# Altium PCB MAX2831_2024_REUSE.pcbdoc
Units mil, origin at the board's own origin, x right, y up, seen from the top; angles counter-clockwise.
Board outline 3396.87 x 1187.57 mil, 6 copper layers (Top Layer, Inner1, Inner2, Inner3, Inner4, Bottom Layer); 31 components, 42 nets, 128 pads, 28 vias.
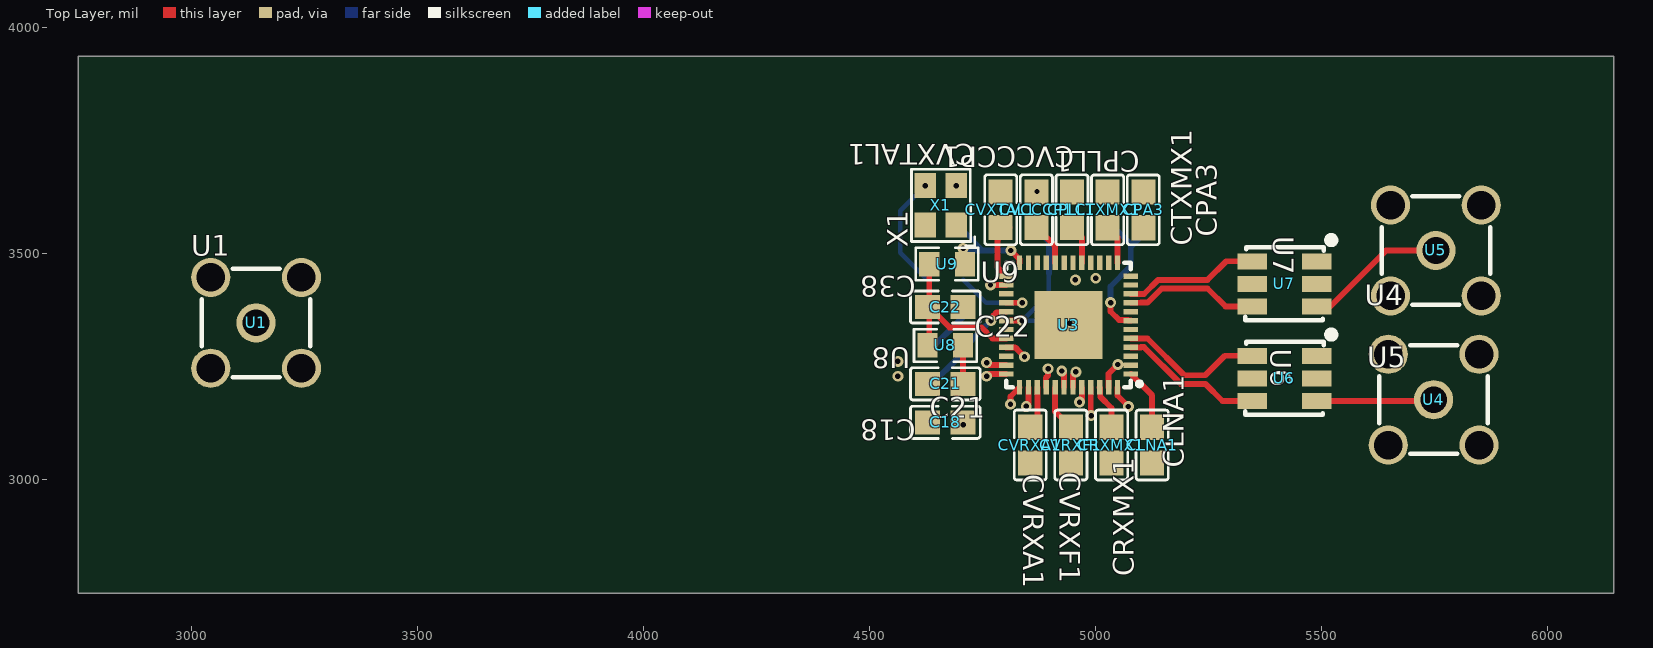
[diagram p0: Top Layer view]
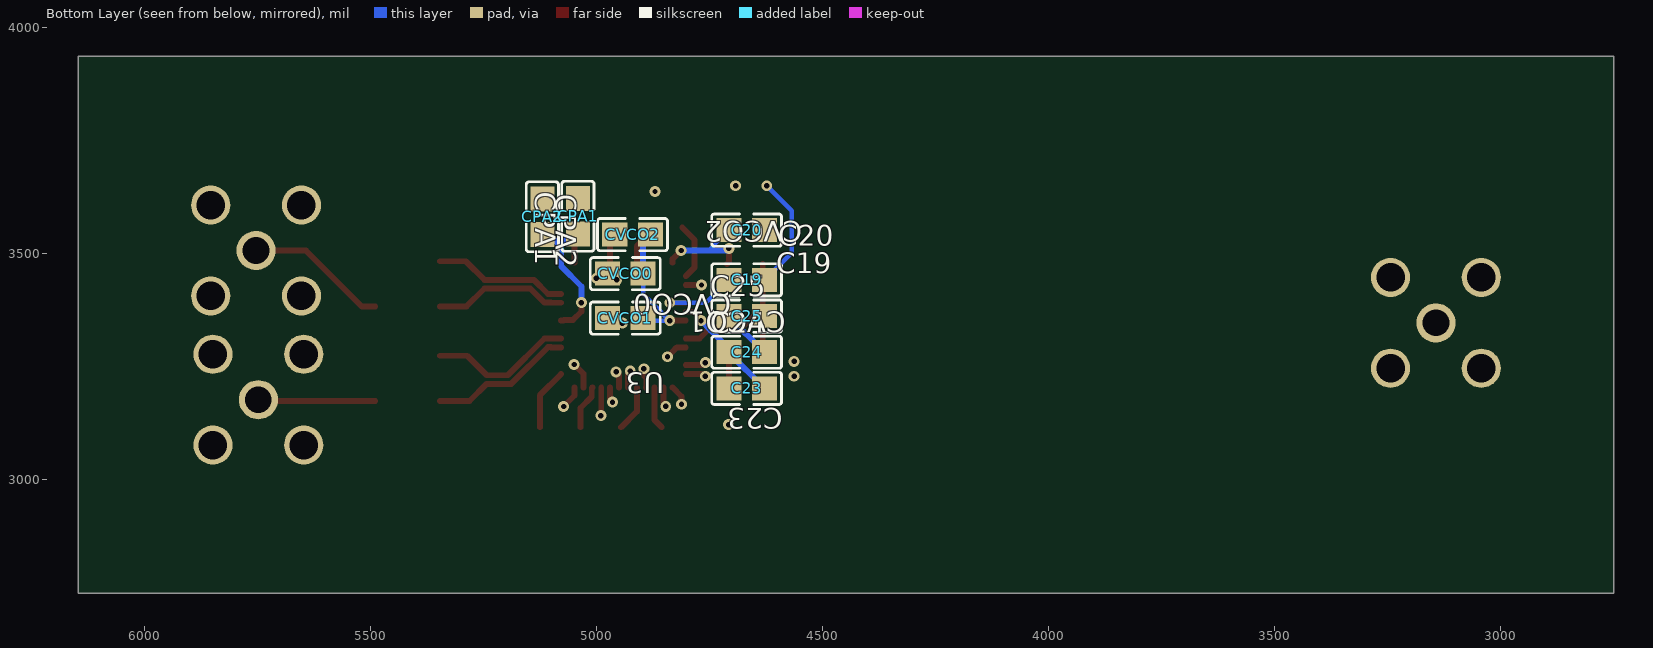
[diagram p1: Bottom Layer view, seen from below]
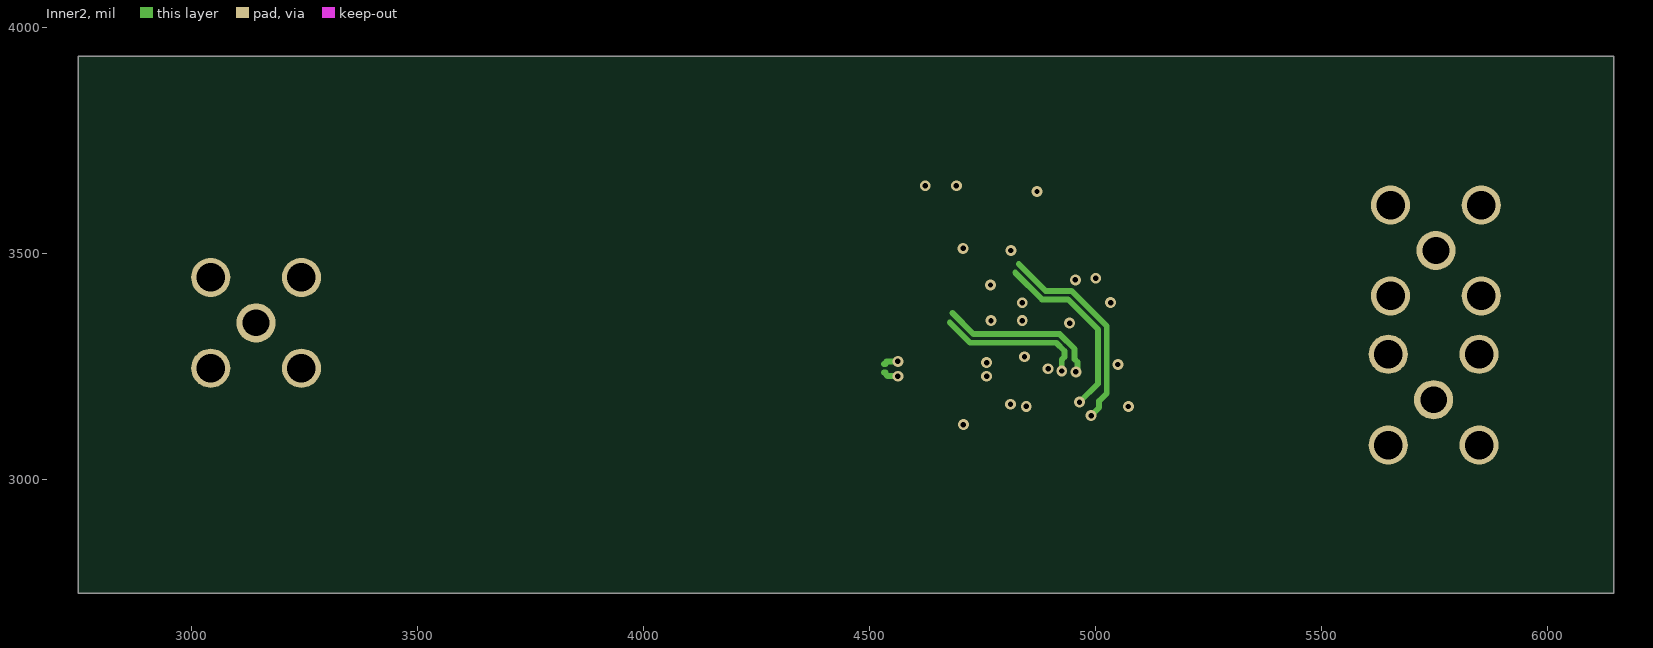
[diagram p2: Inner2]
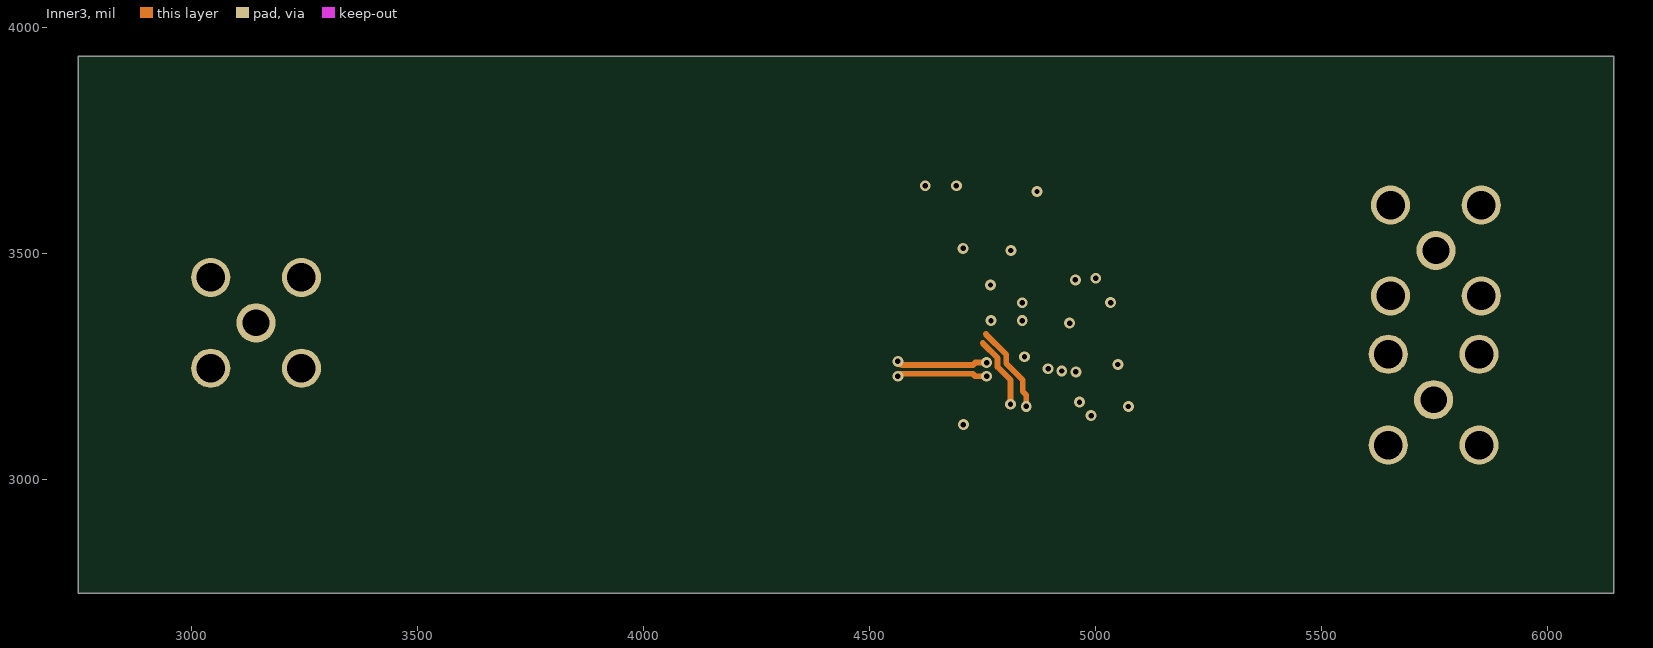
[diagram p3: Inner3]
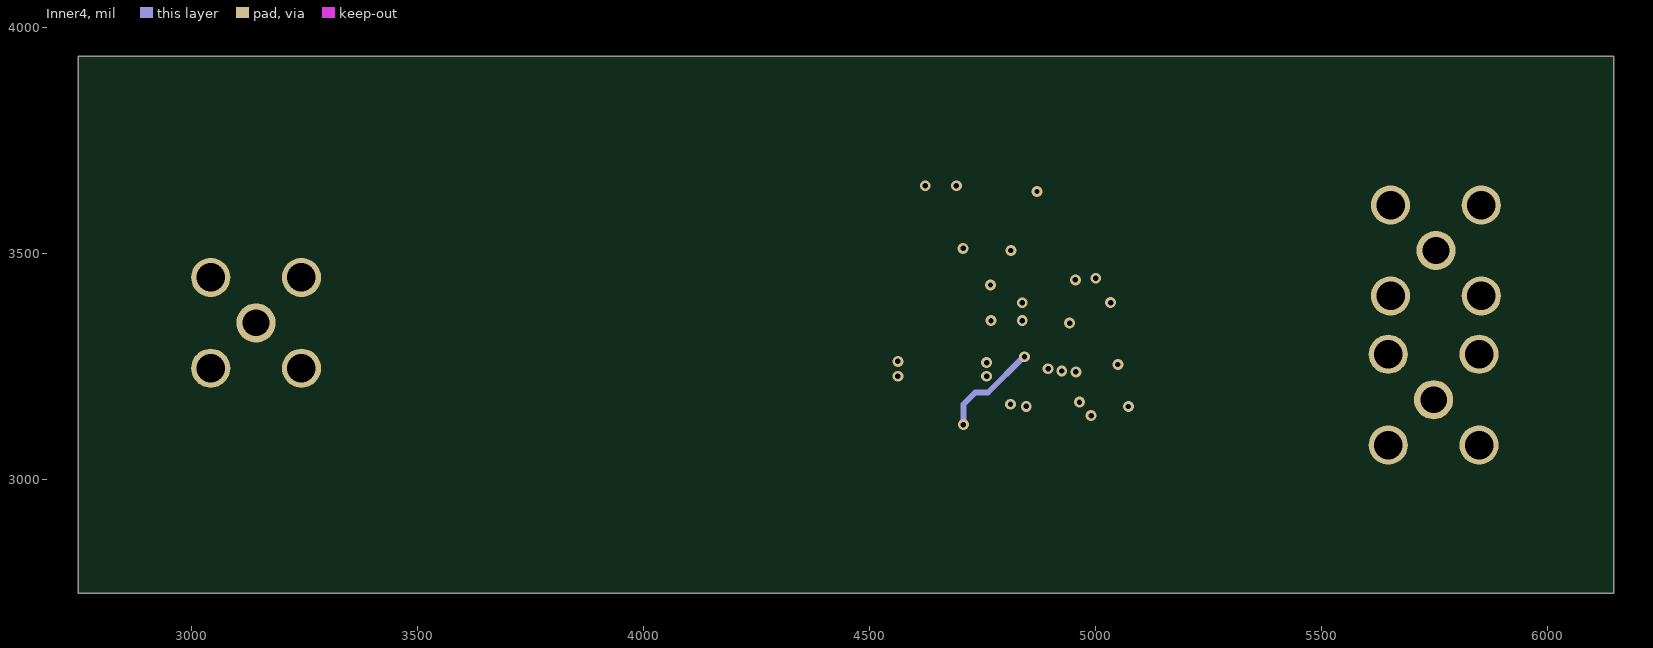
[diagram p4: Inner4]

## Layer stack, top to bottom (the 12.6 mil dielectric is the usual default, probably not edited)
Top Layer: signal copper (thickness not stored)
Dielectric: dielectric 12.6, FR-4, Dk 4.8
Inner1: signal copper (thickness not stored)
Dielectric: dielectric 12.6, FR-4, Dk 4.8
Inner2: signal copper (thickness not stored)
Dielectric: dielectric 12.6, FR-4, Dk 4.8
Inner3: signal copper (thickness not stored)
Dielectric: dielectric 12.6, FR-4, Dk 4.8
Inner4: signal copper (thickness not stored)
Dielectric: dielectric 12.6, FR-4, Dk 4.8
Bottom Layer: signal copper (thickness not stored)

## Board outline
6146.87,2750 2750,2750 2750,3937.57 6146.87,3937.57

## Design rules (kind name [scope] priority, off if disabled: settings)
BoardOutlineClearance copperThickness1oz [All] p0: genericclearance=10 ignorepadtopadclearanceinfootprint=FALSE except(0: Arc-SplitContinuation Track-SplitContinuation SMDPad-SplitContinuation THPad-SplitContinuation Via-SplitContinuation Fill-SplitContinuation Poly-SplitContinuation Region-SplitContinuation Text-SplitContinuation; 6: Track-CutoutEdge SMDPad-CutoutEdge THPad-CutoutEdge Via-CutoutEdge Region-CutoutEdge; 11.8: Track-OutlineEdge SMDPad-OutlineEdge THPad-OutlineEdge Via-OutlineEdge Fill-OutlineEdge Region-OutlineEdge Poly-OutlineEdge Text-OutlineEdge Fill-CutoutEdge)
BoardOutlineClearance copperThickness2oz [All] p0: genericclearance=10 ignorepadtopadclearanceinfootprint=FALSE except(0: Arc-SplitContinuation Track-SplitContinuation SMDPad-SplitContinuation THPad-SplitContinuation Via-SplitContinuation Fill-SplitContinuation Poly-SplitContinuation Region-SplitContinuation Text-SplitContinuation; 6: Track-CutoutEdge SMDPad-CutoutEdge THPad-CutoutEdge Via-CutoutEdge Region-CutoutEdge; 11.8: Track-OutlineEdge SMDPad-OutlineEdge THPad-OutlineEdge Via-OutlineEdge Fill-OutlineEdge Region-OutlineEdge Poly-OutlineEdge Text-OutlineEdge Fill-CutoutEdge)
Clearance copperThickness1oz [(InNet('3.3') OR InNet('GND') OR InNet('RXQN') OR InNet('RXQP') OR InNet('RXIN') OR InNet('RXIP') OR InNet('TXQN') OR InNet('TXQP') OR InNet('TXIN') OR InNet('TXIP') OR InNet('$1I297\$1N2490') OR InNet('$1I297\$1N2254') OR InNet('$1I297\XTAL') OR InNet('$1I297\CPOUT') OR InNet('$1I297\RXN') OR InNet('$1I297\TXN') OR InNet('$1I297\RXP') OR InNet('$1I297\TXP') OR InNet('$1I297\$1N1514') OR InNet('$1I297\$1N1513') OR InNet('$1I297\BYPASS') OR InNet('$1I297\RXTX_MODE') OR InNet('$1I297\RXHP') OR InNet('$1I297\TUNE') OR InNet('$1I297\$1N1515') OR InNet('REF') OR InNet('$1I297\SHDN#') OR InNet('+5V') OR InNet('$1I297\D6') OR InNet('$1I297\D7') OR InNet('$1I297\D3') OR InNet('$1I297\D2') OR InNet('$1I297\D4') OR InNet('$1I297\D5') OR InNet('$1I297\CS#') OR InNet('$1I297\RSSI') OR InNet('$1I297\SCLK') OR InNet('$1I297\DIN') OR InNet('$1I297\CLKBUF') OR InNet('$1I297\PLL_LOCK') OR InNet('$1I297\D1') OR InNet('$1I297\$1N3884'))] p1: gap=7 ignorepadtopadclearanceinfootprint=FALSE except(4: Track-Track; 6: Track-SMDPad SMDPad-SMDPad Track-THPad SMDPad-THPad THPad-THPad Track-Via SMDPad-Via THPad-Via Via-Via SMDPad-Fill THPad-Fill Via-Fill Fill-Fill Track-Region SMDPad-Region THPad-Region Via-Region Region-Region Track-Poly SMDPad-Poly THPad-Poly Via-Poly Fill-Poly Region-Poly Poly-Poly Track-Text SMDPad-Text THPad-Text Via-Text Fill-Text Region-Text Poly-Text Text-Text; 6.9: Track-Hole SMDPad-Hole THPad-Hole Via-Hole Fill-Hole Region-Hole Poly-Hole Text-Hole Sheet-Hole; 11.8: Track-Fill Fill-Region Track-Sheet SMDPad-Sheet THPad-Sheet Via-Sheet Fill-Sheet Region-Sheet Poly-Sheet Text-Sheet)
Clearance copperThickness2oz [All] p1: gap=7 ignorepadtopadclearanceinfootprint=FALSE except(6: Track-SMDPad SMDPad-SMDPad Track-THPad SMDPad-THPad THPad-THPad Track-Via SMDPad-Via THPad-Via Via-Via SMDPad-Fill THPad-Fill Via-Fill Fill-Fill Track-Region SMDPad-Region THPad-Region Via-Region Region-Region Track-Poly SMDPad-Poly THPad-Poly Via-Poly Fill-Poly Region-Poly Poly-Poly Track-Text SMDPad-Text THPad-Text Via-Text Fill-Text Region-Text Poly-Text Text-Text; 6.9: Track-Hole SMDPad-Hole THPad-Hole Via-Hole Fill-Hole Region-Hole Poly-Hole Text-Hole Sheet-Hole; 8: Track-Track; 11.8: Track-Fill Fill-Region Track-Sheet SMDPad-Sheet THPad-Sheet Via-Sheet Fill-Sheet Region-Sheet Poly-Sheet Text-Sheet)
DiffPairsRouting differentialPair [All] p1: maxuncoupledlength=10 minlimit=6 maxlimit=6 mostfreqgap=6 toplayer_minwidth=5 toplayer_prefwidth=10 toplayer_maxwidth=100 bottomlayer_minwidth=5 bottomlayer_prefwidth=10 bottomlayer_maxwidth=100 midlayer1_minwidth=5 midlayer1_prefwidth=10 midlayer1_maxwidth=100 midlayer2_minwidth=5 midlayer2_prefwidth=10 midlayer2_maxwidth=100 midlayer3_minwidth=5 midlayer3_prefwidth=10 midlayer3_maxwidth=100 midlayer4_minwidth=5 midlayer4_prefwidth=10 midlayer4_maxwidth=100
PasteMaskExpansion pasteMaskExpansion [All] p1: expansion=0
PlaneConnect innerPlane [All] p1: planeconnectstyle=Relief reliefexpansion=20 reliefentries=4 reliefconductorwidth=10 reliefairgap=10
PolygonConnect copperRegion [All] p1: connectstyle=Relief reliefentries=4 reliefconductorwidth=10 polygonreliefangle="90 Angle" airgapwidth=10
RoutingVias viaSize [All] p1: viastyle="Through Hole" holewidth=12.0078 minholewidth=11.811 maxholewidth=248.0314 width=24.0158 minwidth=19.685 maxwidth=393.7008
SolderMaskExpansion solderMaskExpansion [All] p1: useseparateexpansions=TRUE expansion=2 expansionbottom=2
Width copperThickness1oz [All] p1: maxlimit=100 minlimit=5 preferedwidth=10
Width copperThickness2oz [All] p1: maxlimit=100 minlimit=8 preferedwidth=10

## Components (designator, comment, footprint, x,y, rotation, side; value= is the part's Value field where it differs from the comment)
C18 "CAP_0603" C0805 4668.16,3127.57 r0 top
C19 "CAP_0603" C0805 4668.16,3442.57 r0 bottom
C20 "CAP_0603" C0805 4668.16,3552.57 r0 bottom
C21 "CAP_0603" C0805 4668.16,3212.57 r0 top
C22 "CAP_0603" C0805 4668.16,3382.57 r180 top
C23 "CAP_0603" C0805 4668.16,3202.57 r0 bottom
C24 "CAP_0805" C0805 4668.16,3282.57 r180 bottom
C25 "CAP_0805" C0805 4668.16,3362.57 r180 bottom
CLNA1 "CAP_0603" C0805 5125.6,3077.31 r270 top
CPA1 "CAP_0603" C0805 5041.23,3583.29 r90 bottom
CPA2 "CAP_0603" C0805 5119.97,3582.03 r90 bottom
CPA3 "CAP_0603" C0805 5105.95,3597.31 r90 top
CPLL1 "CAP_0603" C0805 4948.28,3597.66 r90 top
CRXMX1 "CAP_0603" C0805 5035.72,3077.31 r270 top
CTXMX1 "CAP_0603" C0805 5027.11,3597.31 r90 top
CVCCCP1 "CAP_0603" C0805 4869.44,3597.66 r90 top
CVCO0 "CAP_0603" C0805 4936.59,3456.31 r0 bottom
CVCO1 "CAP_0603" C0805 4936.53,3358.12 r0 bottom
CVCO2 "CAP_0603" C0805 4920.6,3542.66 r0 bottom
CVRXA1 "CAP_0603" C0805 4855.95,3077.31 r270 top
CVRXF1 "CAP_0603" C0805 4945.84,3077.31 r270 top
CVXTAL1 "CAP_0603" C0805 4790.6,3597.66 r90 top
U1 "MCX5.08-H5_C9900009324" SMA-TH_MCX5.08-H5 3143.7,3347.57 r0 top
U3 "MAX2831ETM+T" TQFN-48_L7.0-W7.0-P0.50-TL-EP5.6 4940.6,3342.66 r180 top
U4 "MCX5.08-H5_C9900009324" SMA-TH_MCX5.08-H5 5748.16,3177.57 r0 top
U5 "MCX5.08-H5_C9900009324" SMA-TH_MCX5.08-H5 5753.16,3507.57 r0 top
U6 "TCM2-43X+" IND-SMD_6P-L4.1-W3.8-P1.27-TL 5418.16,3224.73 r270 top
U7 "TCM2-43X+" IND-SMD_6P-L4.1-W3.8-P1.27-TL 5418.16,3433.71 r270 top
U8 "SCR0805J1M" R0805 4668.16,3297.57 r0 top
U9 "SCR0805J1M" R0805 4671.9,3477.57 r0 top
X1 "SX3M40.000E20F30THN" OSC-SMD_4P-L3.2-W2.5-BL 4658.16,3607.57 r90 top

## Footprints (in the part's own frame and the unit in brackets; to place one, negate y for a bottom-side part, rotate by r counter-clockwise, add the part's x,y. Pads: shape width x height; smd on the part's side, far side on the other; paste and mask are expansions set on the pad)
C0805 [mm]
  rect 1.41x1.35 smd: 1(-1,0) 2(1,0)
  silkscreen extent -1.96,-0.9 1.96,0.9
IND-SMD_6P-L4.1-W3.8-P1.27-TL [mm]
  rect 0.9x1.657 smd: 1(-1.27,1.814) 2(0,1.814) 3(1.27,1.814) 4(1.27,-1.814) 5(0,-1.814) 6(-1.27,-1.814)
  silkscreen extent -2.66,-2.2 2.05,2.83
OSC-SMD_4P-L3.2-W2.5-BL [mm]
  rect 1.4x1.2 smd: 1(-1.1,-0.875) 2(1.1,-0.875) 3(1.1,0.875) 4(-1.1,0.875)
  silkscreen extent -2.29,-1.9 2.03,1.65
R0805 [mm]
  rect 1.133x1.377 smd: 1(-1,0) 2(1,0)
  silkscreen extent -1.76,-0.92 1.76,0.92
SMA-TH_MCX5.08-H5 [mm]
  round 2.2 hole 1.6: 1(-2.55,-2.55) 2(-2.55,2.55) 3(2.55,2.55)
  round 2.2 hole 1.6 copper offset 0,0: 4(2.55,-2.55)
  round 2.2 hole 1.5: 5(0,0)
  silkscreen extent -3.05,-3.05 3.05,3.05
TQFN-48_L7.0-W7.0-P0.50-TL-EP5.6 [mm]
  rect 0.8x0.3 smd: 1(-3.5,2.751) 2(-3.5,2.25) 3(-3.5,1.75) 4(-3.5,1.251) 5(-3.5,0.75) 6(-3.5,0.251) 7(-3.5,-0.249) 8(-3.5,-0.749) 9(-3.5,-1.25) 10(-3.5,-1.75) 11(-3.5,-2.249) 12(-3.5,-2.748) 25(3.5,-2.748) 26(3.5,-2.249) 27(3.5,-1.75) 28(3.5,-1.25) 29(3.5,-0.749) 30(3.5,-0.249) 31(3.5,0.251) 32(3.5,0.75) 33(3.5,1.251) 34(3.5,1.75) 35(3.5,2.25) 36(3.5,2.751)
  rect 0.3x0.8 smd: 13(-2.751,-3.5) 14(-2.251,-3.5) 15(-1.75,-3.5) 16(-1.25,-3.5) 17(-0.749,-3.5) 18(-0.25,-3.5) 19(0.249,-3.5) 20(0.749,-3.5) 21(1.25,-3.5) 22(1.75,-3.5) 23(2.251,-3.5) 24(2.751,-3.5) 37(2.751,3.5) 38(2.251,3.5) 39(1.75,3.5) 40(1.25,3.5) 41(0.749,3.5) 42(0.25,3.5) 43(-0.25,3.5) 44(-0.749,3.5) 45(-1.25,3.5) 46(-1.75,3.5) 47(-2.251,3.5) 48(-2.751,3.5)
  rect 3.81x3.81 smd: 49(0,0.001)
  silkscreen extent -4.11,-3.5 3.5,3.5

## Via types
v1: diameter 24.02, hole 12.01, Top Layer to Bottom Layer, 18 vias
v2: diameter 24, hole 12, Top Layer to Bottom Layer, 10 vias

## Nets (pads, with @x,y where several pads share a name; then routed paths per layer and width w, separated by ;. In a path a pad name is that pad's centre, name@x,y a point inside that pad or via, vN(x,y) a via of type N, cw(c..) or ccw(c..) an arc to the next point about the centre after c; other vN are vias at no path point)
3.3: CLNA1.1 CPA1.1 CPA2.1 CPA3.1 CPLL1.1 CRXMX1.1 CTXMX1.1 CVCCCP1.1 CVCO0.1 CVCO1.1 CVCO2.1 CVRXA1.1 CVRXF1.1 CVXTAL1.1 U3.1 U3.7 U3.13 U3.17 U3.20 U3.25 U3.27 U3.30 U3.39 U3.41 U3.46 | length 1479.4
  Top Layer w13: U3.30 v2(4838.16,3352.47) ; U3.25 4783.16,3470.51 4783.16,3530.86 CVXTAL1.1@4810.6,3558.29 ; CVRXA1.1 4871.7,3132.43 U3.39 ; CVCCCP1.1 4911.09,3516.64 U3.20 ; U3.41 4911.09,3151.42 CVRXF1.1 ; CPLL1.1 4970.1,3536.47 U3.17 ; U3.46 5010.81,3203.55 5010.81,3183.95 5035.72,3159.04 CRXMX1.1 ; CTXMX1.1 5048.89,3536.16 U3.13 ; v2(5033.58,3392.47) 5033.39,3392.28 5033.39,3372.86 5052.47,3353.78 5072.08,3353.78 5073.39,3352.47 U3.7 ; U3.1 5125.6,3187.16 CLNA1.1
  Bottom Layer w10: CVCO1.1 4891.51,3352.47 v2(4838.16,3352.47) 4897.22,3411.52 CVCO0.1
  Bottom Layer w13: CVCO2.1 4897.22,3526.67 CVCO0.1 ; v2(5033.58,3392.47) 5033.58,3427.98 5078.16,3472.57 5078.16,3515.86 ; CPA1.1@5041.23,3558.92 5078.16,3521.99 5078.16,3515.86 ; CPA2.1@5119.97,3557.66 5078.16,3515.86
$1I297\$1N1513: U4.5 U6.3 | length 259.8
  Top Layer w13: U6.3 5745.32,3174.73 U4.5
$1I297\$1N1514: U5.5 U7.3 | length 314.9
  Top Layer w13: U7.3 5519.31,3383.71 5643.16,3507.57 U5.5
$1I297\$1N1515: C21.2 U8.2 | length 85
  Top Layer w13: C21.2 U8.2
$1I297\$1N2254: C23.1 C24.1 U3.29 | length 253.2
  Top Layer w13: v1(4769.06,3352.57) 4774.57,3358.07 4774.57,3363.54 4781.88,3370.86 4787.35,3370.86 4788.66,3372.17 U3.29
  Bottom Layer w13: C23.1 4707.53,3281.31 C24.1 4707.53,3290.58 4747.77,3330.82 4747.77,3331.28 v1(4769.06,3352.57)
$1I297\$1N2490: C19.1 X1.3 | length 256.8
  Bottom Layer w10: v1(4623.71,3650.88) 4568.16,3595.33 4568.16,3502.57 4628.16,3442.57 C19.1
$1I297\$1N3884: C25.2
$1I297\BYPASS: C18.2 U3.33 | length 277.8
  Top Layer w13: C18.2 4707.53,3123.2 v2(4708.16,3122.57) ; U3.33 4822.31,3293.42 4823.57,3292.16 4823.72,3292.16 4831.03,3284.84 4831.03,3284.7 v2(4843.16,3272.57)
  Inner4 w13: v2(4708.16,3122.57) 4708.16,3167.57 4734.17,3193.57 4762.55,3193.57 4841.55,3272.57 v2(4843.16,3272.57)
$1I297\CLKBUF: U3.21
$1I297\CPOUT: C20.2 U3.24 U9.2 | length 242.5
  Top Layer w13: v1(4707.53,3512.25) 4707.53,3481.31 U9.2 ; v2(4813.16,3507.57) 4832.29,3488.44 U3.24
  Bottom Layer w10: C20.2 4752.53,3507.57
  Bottom Layer w13: v1(4707.53,3512.25) 4712.22,3507.57 4752.53,3507.57 v2(4813.16,3507.57)
$1I297\CS#: U3.15
$1I297\D1: U3.23
$1I297\D2: U3.11
$1I297\D3: U3.8
$1I297\D4: U3.34
$1I297\D5: U3.14
$1I297\D6: U3.3
$1I297\D7: U3.6
$1I297\DIN: U3.19
$1I297\PLL_LOCK: U3.22
$1I297\RSSI: U3.16
$1I297\RXHP: U3.40 | length 44
  Top Layer w13: U3.40 4890.09,3206.17 4890.09,3225.79 4895.5,3231.19 v1(4895.5,3246.06)
$1I297\RXN: U3.5 U6.6 | length 320
  Top Layer w13: U3.5 5100.64,3313.12 5100.99,3312.77 5115.36,3312.77 5196.56,3231.57 5243.16,3231.57 5286.33,3274.73 U6.6
$1I297\RXP: U3.4 U6.4 | length 317.8
  Top Layer w13: U3.4 5100.64,3293.42 5100.99,3293.77 5107.49,3293.77 5188.69,3212.57 5243.16,3212.57 5281,3174.73 U6.4
$1I297\RXTX_MODE: U3.48 | length 52.4
  Top Layer w13: U3.48 5048.89,3186.84 v1(5073.16,3162.57)
$1I297\SCLK: U3.18
$1I297\SHDN#: U3.12 X1.1
$1I297\TUNE: C22.2 U3.32 U8.1 U9.1 | length 380.6
  Top Layer w13: U8.1 4632.53,3301.31 C22.2@4632.53,3382.57 ; U9.1 C22.2@4632.53,3382.57 ; U3.32 4772.61,3313.12 4748.16,3337.57 4677.53,3337.57 C22.2@4632.53,3382.57
$1I297\TXN: U3.10 U7.6 | length 298.5
  Top Layer w13: U3.10 5100.64,3411.57 5100.99,3411.22 5107.49,3411.22 5138.84,3442.57 5248.16,3442.57 5289.31,3483.71 U7.6
$1I297\TXP: U3.9 U7.4 | length 298
  Top Layer w13: U3.9 5100.64,3391.87 5100.99,3392.22 5115.36,3392.22 5146.71,3423.57 5248.16,3423.57 5288.02,3383.71 U7.4
$1I297\XTAL: C19.2 C24.2 C25.1 U3.28 | length 299.6
  Top Layer w13: U3.28 v2(4838.16,3391.87)
  Bottom Layer w10: C19.2 4758.23,3391.87 v2(4838.16,3391.87)
  Bottom Layer w13: C24.2 4707.53,3361.31 C25.1
+5V: X1.4
GND: C18.1 C20.1 C21.1 C22.1 C23.2 CLNA1.2 CPA1.2 CPA2.2 CPA3.2 CPLL1.2 CRXMX1.2 CTXMX1.2 CVCCCP1.2 CVCO0.2 CVCO1.2 CVCO2.2 CVRXA1.2 CVRXF1.2 CVXTAL1.2 U1.1 U1.2 U1.3 U1.4 U3.2 U3.26 U3.31 U3.47 U3.49 U4.1 U4.2 U4.3 U4.4 U5.1 U5.2 U5.3 U5.4 U6.1 U6.2 U7.1 U7.2 X1.2 | length 93.9
  Top Layer w13: v2(4767.96,3431.22) U3.26 ; U3.47 5029.2,3234.99 v1(5049.64,3255.42)
  other v1: 4942.91,3347.11 4955.9,3442.57 5000.9,3446.31 4870.9,3638.12 4692.61,3650.88
REF: U1.5
RXIN: U3.37 | length 206.3
  Top Layer w13: v1(4812.29,3167.47) 4812.29,3184.87 U3.37
  Inner3 w13: 4750.84,3302.66 4783.79,3269.71 4783.79,3249.9 4812.29,3221.39 v1(4812.29,3167.47)
RXIP: U3.38 | length 234.1
  Top Layer w13: v1@4851.99,3167.66 U3.38
  Inner3 w13: 4757.71,3322.66 4802.79,3277.58 4802.79,3257.77 4839.25,3221.31 4839.25,3195.85 4847.21,3187.89 v1(4847.21,3162.88)
RXQN: U3.35 | length 283.2
  Top Layer w13: v1(4759.29,3259.57) 4764.79,3254.07 U3.35
  Inner2 w13: 4535.6,3256.66 4532.67,3256.66 4538.16,3262.15 v2(4563.16,3262.15)
  Inner3 w13: v2(4563.16,3262.15) 4571.25,3254.07 4728.79,3254.07 4734.29,3259.57 v1(4759.29,3259.57)
RXQP: U3.36 | length 282.9
  Top Layer w13: v1(4759.29,3229.57) 4764.09,3234.37 U3.36
  Inner2 w13: 4535.6,3237.66 4532.67,3237.66 4540.75,3229.58 v2(4563.16,3229.58)
  Inner3 w13: v2(4563.16,3229.58) 4568.65,3235.07 4728.79,3235.07 4734.29,3229.57 v1(4759.29,3229.57)
TXIN: U3.44 | length 447.2
  Top Layer w13: v1(4964.95,3172.32) 4970.1,3177.47 U3.44
  Inner2 w13: 4822.73,3458.66 4882.31,3399.07 4939.69,3399.07 5005.6,3333.17 5005.6,3212.97 v1(4964.95,3172.32)
TXIP: U3.45 | length 526.7
  Top Layer w13: U3.45 4989.79,3142.95 v1(4990.4,3142.35)
  Inner2 w13: 4830.6,3477.66 4890.18,3418.07 4947.56,3418.07 5025.15,3340.49 5025.15,3191.37 5008.09,3174.31 5008.09,3160.03 v1(4990.4,3142.35)
TXQN: U3.42 | length 365.3
  Top Layer w13: v1(4925.5,3241.11) 4930.74,3235.86 U3.42
  Inner2 w13: 4677.89,3348.5 4722.73,3303.66 4913.44,3303.66 4931.75,3285.35 4931.75,3272.35 4925.5,3266.11 v1(4925.5,3241.11)
TXQP: U3.43 | length 394.2
  Top Layer w13: U3.43 4950.45,3232.52 v2(4957,3239.06)
  Inner2 w13: 4684.3,3368.96 4730.6,3322.66 4921.31,3322.66 4954.05,3289.92 4954.05,3267 4960.3,3260.75 4960.3,3242.37 v2(4957,3239.06)
pads on no net: U6.5 U7.5

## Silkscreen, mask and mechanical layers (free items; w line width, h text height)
Top Silkscreen Layer:
  text "C38" at 4602.95,3450.4 h45 r180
